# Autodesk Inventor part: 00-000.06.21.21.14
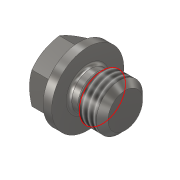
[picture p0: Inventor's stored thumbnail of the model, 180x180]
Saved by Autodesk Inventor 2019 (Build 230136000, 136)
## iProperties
Created: 2019-01
Part Number: 00-000.06.21.21.14
Material: Steel, Mild
Document SubType Name: Modeling
Designer: m.vorobev
Density: 7.85 g/cm^3
Appearance: Semi-Polished
Author: m.vorobev
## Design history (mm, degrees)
sketch "Sketch1"
  geometry: L1 (0, 0)-(-8, 0); L2 (-8, 0)-(-8, 11); L3 (-8, 11)-(0, 11); L4 (0, 11)-(0, 0); L5 (0, 0)-(3, 0); L6 (3, 0)-(3, 12.5); L7 (3, 12.5)-(0, 12.5); L8 (0, 12.5)-(0, 0); L9 (8, 0)-(16, 0); L10 (16, 0)-(16, 8); L11 (16, 8)-(8, 8); L12 (8, 8)-(8, 0); L13 (8, 8)-(6.5, 6.5); L14 (6.5, 6.5)-(3, 6.5); L15 (3, 0)-(8, 0); L16 (-8, 9)-(-6.845, 11); 1 further point
  constraints: 32 end point, 6 parallel, 5 horizontal, 4 point on line, 3 perpendicular, 1 coincident
  dimensions: "d0" = 45 deg angle of L14 L13; "d1" = 25 diameter of L7 L1; "d2" = 24 distance between parallel lines of L10 L2; "d3" = 8 distance of L2.end L3.end; "d4" = 13 distance between parallel lines of L10 L6; "d5" = 16 diameter of L11 L1; "d6" = 5 distance between parallel lines of L12 L6; "d7" = 13 diameter of L14 L1; "d8" = 22 diameter of L3 L1; "d16" = 18 diameter of L16.start L1; "d17" = 30 deg angle of L16 L2
revolve "Revolution1" sketch "Sketch1" stored, may be unused: angle "d9" = 90 deg
chamfer "Chamfer1" distance "d10" = 2; stored, may be unused: second distance "d11" = 2, angle "d12" = 45 deg
sketch "Sketch2"
  geometry: L1 (0, 10.97)-(9.5, 5.485); L2 (9.5, 5.485)-(9.5, -5.485); L3 (9.5, -5.485)-(0, -10.97); L4 (0, -10.97)-(-9.5, -5.485); L5 (-9.5, -5.485)-(-9.5, 5.485); L6 (-9.5, 5.485)-(0, 10.97); C1 r 17.845 at (0, 0); 2 further points
  constraints: 12 end point, 2 coincident, 1 centre point, 1 vertical, 13 other
  dimensions: "d13" = 19 distance between parallel lines of L5 L2
extrude "Extrusion1" cut sketch "Sketch2" stored distance "d14" = 10; taper "d15" = 0 deg
thread "Thread1" dims "d18" = 10, "d19" = 0
fillet "Fillet1" dims "d20" = 1
body "Solid1"
